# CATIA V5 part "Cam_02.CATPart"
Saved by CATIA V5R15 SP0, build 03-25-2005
Part number: Cam_02
Material "Pastel Green": density 7860 kg/m3, Young's modulus 2e+11 Pa, Poisson ratio 0.266
Bounding box of the stored display mesh (mm): x 0 to 77, y -37 to 37, z -117 to 37
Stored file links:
  E:\#01 CATIA Lecture Materials\#06 DMU\#11 DMU Page01 KIN EX11\Cam_02.CATPart
  D:\공학과제\모델링\prodo(shaft1).CATPart
  C:\Program Files\Dassault Systemes\B20\win_b64\startup\materials\Catalog.CATMaterial
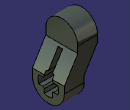
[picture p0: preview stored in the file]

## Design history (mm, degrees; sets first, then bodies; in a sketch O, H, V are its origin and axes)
Body1 (main body), material "Pastel Green"
  Sketch1 on yz-plane, origin (0, 0, 0), H (0, 1, 0), V (0, 0, 1)
    arc A1 centre (0, 0) radius 37 from (37, 0) to (-37, 0) ccw
    point P1 (0, 37)
    construction line L1 (0, 37) -> (0, -117)
    point P2 (0, -117)
    arc A2 centre (0, -80) radius 37 from (-37, -80) to (37, -80) ccw
    point P3 (0, -80)
    point P4 (-37, 0)
    line L2 (-37, 0) -> (-37, -80)
    point P6 (37, 0)
    line L3 (37, 0) -> (37, -80)
    radius A1 = 37
    length L1 = 154
    radius A2 = 37
    coincidence: P1 A1, P1 V, A2 P2, P3 L1, P4 H, P6 H
    vertical: L1 V
    tangency: L2 A1, L3 A2
  Pad1: profile Sketch1, direction (1, 0, 0), length 77
  Sketch2 on zx-plane, origin (0, 0, 0), H (-1, 0, 0), V (0, 0, 1)
    line L1 (-46, 37) -> (-46, -15)
    line L2 (-46, -15) -> (-77, -65)
    point P3 (-77, -65)
    line L3 (-77, -65) -> (-77, 37)
    line L4 (-77, 37) -> (-46, 37)
    line L5 (0, -15) -> (-31, -65)
    line L6 (-31, -65) -> (-31, -117)
    line L7 (-31, -117) -> (0, -117)
    line L8 (0, -117) -> (0, -15)
    reference projected line E1 (-77, -117) -> (-77, -80) from edge [face of Pad1 from Sketch1.A2 | end face of Pad1]
    reference intersected line E2 (-77, 37) -> (0, 37) from face of Pad1 from Sketch1.A1
    reference intersected line E3 (0, -117) -> (-77, -117) from face of Pad1 from Sketch1.A2
    reference intersected line E4 (0, 37) -> (0, -117) from start face of Pad1
    reference intersected line E5 (-77, -117) -> (-77, 37) from end face of Pad1
    distance E1 L6 = 46
    distance L1 V = 46
    length L1 = 52
    length L6 = 52
    distance P3 L7 = 52
    vertical: L1 V, L3 V, L6 V
    horizontal: L4 H, L7 H
    coincidence: E3 L7, L4 E2, L8 E4, E5 L3
    parallelism: L5 L2
  Pocket1: profile Sketch2, direction (0, -1, 0), through (limit type 6), opposite side length 77
  Sketch3 on xy-plane, origin (0, 0, 0), H (1, 0, 0), V (0, 1, 0)
    arc A1 centre (0, 0) radius 23.8 from (21.9289, -9.25) to (21.9289, 9.25) ccw
    line L1 (-21.9289, 9.25) -> (-9.25, 9.25)
    line L2 (21.9289, -9.25) -> (9.25, -9.25)
    line L3 (9.25, 21.9289) -> (9.25, 9.25)
    line L4 (-9.25, -21.9289) -> (-9.25, -9.25)
    point P4 (-9.25, -21.9289)
    arc A2 centre (0, 0) radius 23.8 from (-9.25, -21.9289) to (9.25, -21.9289) ccw
    point P6 (-21.9289, 9.25)
    arc A3 centre (0, 0) radius 23.8 from (-21.9289, 9.25) to (-21.9289, -9.25) ccw
    point P8 (9.25, 21.9289)
    arc A4 centre (0, 0) radius 23.8 from (9.25, 21.9289) to (-9.25, 21.9289) ccw
    point P9 (-9.25, 9.25)
    line L5 (9.25, 9.25) -> (21.9289, 9.25)
    line L6 (9.25, -9.25) -> (9.25, -21.9289)
    line L7 (-9.25, 9.25) -> (-9.25, 21.9289)
    point P12 (-9.25, -9.25)
    line L8 (-9.25, -9.25) -> (-21.9289, -9.25)
    radius A1 = 23.8
    distance L1 L2 = 18.5
    distance H L1 = 9.25
    distance L3 L4 = 18.5
    distance V L3 = 9.25
    horizontal: L1 H, L2 H, L5 H, L8 H
    vertical: L3 V, L4 V, L6 V, L7 V
    coincidence: A1 P4, A1 A2, A1 P6, A1 A3, A1 P8, A1 A4, L4 P9, L1 L5, L3 L6, L2 P12, L4 L7, L2 L8
  Sketch4 on start face of Pad1, origin (0, 0, 0), H (0, -1, 0), V (0, 0, 1)
    construction line L1 through (-1.3128, 0) direction (1, 0)
    line L2 (-21.9289, 9.25) -> (-9.25, 9.25)
    line L3 (21.9289, -9.25) -> (9.25, -9.25)
    construction line L4 through (0, 0) direction (0, 1)
    line L5 (9.25, 21.9289) -> (9.25, 9.25)
    line L6 (-9.25, -21.9289) -> (-9.25, -9.25)
    point P1 (-9.25, -21.9289)
    arc A1 centre (0, 0) radius 23.8 from (21.9289, -9.25) to (21.9289, 9.25) ccw
    point P2 (-21.9289, 9.25)
    point P3 (9.25, 21.9289)
    arc A2 centre (0, 0) radius 23.8 from (9.25, 21.9289) to (-9.25, 21.9289) ccw
    point P4 (-9.25, 9.25)
    line L7 (9.25, 9.25) -> (21.9289, 9.25)
    line L8 (9.25, -9.25) -> (9.25, -21.9289)
    point P5 (-9.25, -9.25)
    line L9 (-9.25, 9.25) -> (-9.25, 21.9289)
    line L10 (-9.25, -9.25) -> (-21.9289, -9.25)
    point P6 (0, 0)
    arc A3 centre (0, 0) radius 23.8 from (-9.25, -21.9289) to (9.25, -21.9289) ccw
    arc A4 centre (0, 0) radius 23.8 from (-21.9289, 9.25) to (-21.9289, -9.25) ccw
    radius A4 = 23.8
    distance L5 L9 = 18.5
    distance L7 L3 = 18.5
    horizontal: L2 L1, L3 L1, L7 L1, L10 L1
    vertical: L5 L4, L6 L4, L8 L4, L9 L4
    coincidence: A1 P1, A1 P2, A1 P3, A1 A2, L6 P4, L2 L7, L5 L8, L3 P5, L6 L9, L10 L3, L4 V, L1 H, P6 L1
    symmetry: L5 L9 L4, A1 A4 L4, L7 L3 L1
  Pocket2: profile Sketch4, direction (1, 0, 0), length 35
  Sketch5 on end face of Pad1, origin (77, 0, 0), H (0, 1, 0), V (0, 0, 1)
    point P1 (9.25, -89.25)
    point P2 (21.9289, -89.25)
    point P3 (21.9289, -70.75)
    point P4 (21.9289, -89.25)
    point P5 (21.9289, -70.75)
    point P6 (9.25, -70.75)
    point P7 (9.25, -70.75)
    point P8 (9.25, -58.0711)
    point P9 (-9.25, -58.0711)
    point P10 (9.25, -58.0711)
    point P11 (-9.25, -58.0711)
    point P12 (-9.25, -70.75)
    point P13 (-9.25, -70.75)
    point P14 (-21.9289, -70.75)
    point P15 (-21.9289, -89.25)
    point P16 (-21.9289, -70.75)
    point P17 (-21.9289, -89.25)
    point P18 (-9.25, -89.25)
    point P19 (-9.25, -89.25)
    point P20 (-9.25, -101.9289)
    point P21 (9.25, -101.9289)
    point P22 (-9.25, -101.9289)
    point P23 (9.25, -101.9289)
    point P24 (9.25, -89.25)
    line L1 (21.9289, -89.25) -> (9.25, -89.25)
    arc A1 centre (0, -80) radius 23.8 from (21.9289, -89.25) to (21.9289, -70.75) ccw
    line L2 (9.25, -70.75) -> (21.9289, -70.75)
    line L3 (9.25, -58.0711) -> (9.25, -70.75)
    arc A2 centre (0, -80) radius 23.8 from (9.25, -58.0711) to (-9.25, -58.0711) ccw
    line L4 (-9.25, -70.75) -> (-9.25, -58.0711)
    line L5 (-21.9289, -70.75) -> (-9.25, -70.75)
    arc A3 centre (0, -80) radius 23.8 from (-21.9289, -70.75) to (-21.9289, -89.25) ccw
    line L6 (-9.25, -89.25) -> (-21.9289, -89.25)
    line L7 (-9.25, -101.9289) -> (-9.25, -89.25)
    arc A4 centre (0, -80) radius 23.8 from (-9.25, -101.9289) to (9.25, -101.9289) ccw
    line L8 (9.25, -89.25) -> (9.25, -101.9289)
    construction circle A5 centre (0, -80) radius 23.8
    point P25 (0, -80)
    point P26 (23.5231, -83.6201)
    construction line L9 (-50.1073, -80) -> (73.8344, -80)
    axis line L10 (0, -132.723) -> (0, -41.3575)
    reference projected arc E1 centre (0, -80) radius 37 from (-37, -80) to (37, -80) ccw from edge [face of Pad1 from Sketch1.A2 | end face of Pad1]
    distance L5 L6 = 18.5
    distance L7 L8 = 18.5
    radius A1 = 23.8
    concentricity: P25 A1, P25 E1
    coincidence: A5 P26, P26 A1, A1 A5, A5 A4, A5 A3, A2 A5, P25 L10, L9 P25, P2 P4, P3 P5, P6 P7, P8 P10, P11 P9, P14 P16, P13 P12, P18 P19, P24 P1, P17 P15, P23 P21, P20 P22, L3 L8, L4 L7, L1 L6, L2 L5
    horizontal: L9 H
    vertical: L10 V
    symmetry: L6 L5 L9, L8 L7 L10
  Pocket3: profile Sketch5, direction (-1, 0, 0), length 35
  Sketch6 on start face of Pad1, origin (0, 0, 0), H (0, -1, 0), V (0, 0, 1)
    line L1 (-5, -20) -> (5, -20)
    line L2 (5, -20) -> (5, -60)
    line L3 (5, -60) -> (-5, -60)
    line L4 (-5, -60) -> (-5, -20)
    length L1 = 10
    distance L1 L3 = 40
    distance L1 H = 20
    horizontal: L1 H, L3 H
    vertical: L2 V, L4 V
    symmetry: L4 L2 V
  Pocket4: profile Sketch6, direction (1, 0, 0), through (limit type 6)
  Fillet1: radius 3, on edge [face of Pocket3 from Sketch5.L5 | face of Pocket3 from Sketch5.L4]; edge [face of Pocket3 from Sketch5.L7 | face of Pocket3 from Sketch5.L6]; edge [face of Pocket3 from Sketch5.L1 | face of Pocket3 from Sketch5.L8]; edge [face of Pocket3 from Sketch5.L3 | face of Pocket3 from Sketch5.L2]; edge [face of Pocket2 from Sketch4.L5 | face of Pocket2 from Sketch4.L7]; edge [face of Pocket2 from Sketch4.L2 | face of Pocket2 from Sketch4.L9]; edge [face of Pocket2 from Sketch4.L6 | face of Pocket2 from Sketch4.L10]; edge [face of Pocket2 from Sketch4.L3 | face of Pocket2 from Sketch4.L8]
